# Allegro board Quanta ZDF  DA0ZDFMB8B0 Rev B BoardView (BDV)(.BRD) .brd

Outline 153.3 x 69.5 mm; copper layers: TOP, IN1, IN2, GND, IN3, IN4, IN5, BOTTOM. Coordinates in mm from the lower left corner of the outline.
Outline path: 0,62.4 arc(0.29,63.11) 1,63.4 17.2,63.4 arc(18.61,62.81) 19.2,61.4 19.2,52.9 arc(19.79,51.49) 21.2,50.9 56.5,50.9 arc(57.91,51.49) 58.5,52.9 58.5,65.5 arc(59.67,68.33) 62.5,69.5 148,69.5 arc(148.71,69.21) 149,68.5 149,65.2 152.3,65.2 arc(153.01,64.91) 153.3,64.2 153.3,6 arc(152.71,4.59) 151.3,4 88.1,4 arc(87.39,3.71) 87.1,3 87.1,1 arc(86.81,0.29) 86.1,0 9.2,0 arc(7.79,0.59) 7.2,2 7.2,20 4.2,20 arc(2.79,20.59) 2.2,22 2.2,40.1 13.45,40.1 arc(13.95,40.6) 13.45,41.1 13.45,46.65 arc(13.95,47.15) 13.45,47.65 2.2,47.65 2.2,47.75 1,47.75 arc(0.29,48.04) 0,48.75 0,51.73 4.27,51.73 arc(4.77,51.22) 5.27,51.73 5.27,60.68 arc(4.77,61.17) 4.27,60.68 0,60.68 0,62.4

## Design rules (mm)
constraint set DEFAULT: min track width 0.089
net group DFP-S3W10-T12345B: nets EAR_JACK_GND MIC_P
net group W5-T12345B: nets DVDD_CORE PP5000_PMIC
net group W6-T1234B: nets USB_C0_CC1 USB_C0_CC2
net group W10-T1234B: nets AMP_L_EN AMP_R_EN
net group W16-T12345B: nets DVDD_SRAM_PROC_B PP3000_EMMC
net group W20-T123B: nets DA7219_HPL HP_R
net group DFP-S3.5(3: nets 3V3_PCSCL 3V3_PCSDA SOC_I2C5_1V8_SCL SOC_I2C5_1V8_SDA SOC_I2C6_1V8_SCL SOC_I2C6_1V8_SDA
net group DFP-S3.5(3: nets AP_CTS_BT_RTS AP_RTS_BT_CTS AP_RXD1_BT_TXD AP_TXD1_BT_RXD CTP_I2C_SCL CTP_I2C_SDA EC_I2C1_1V8_SCL EC_I2C1_1V8_SDA EC_I2C2_1V8_SCL EC_I2C2_1V8_SDA EC_I2C_USB_C0_MUX_SCL EC_I2C_USB_C0_MUX_SDA I2C_SCL_INA I2C_SCL_INA_SERVO I2C_SDA_INA I2C_SDA_INA_SERVO SOC_I2C0_1V8_SCL SOC_I2C0_1V8_SDA SOC_I2C2_1V8_SCL SOC_I2C2_1V8_SDA SOC_I2C3_1V8_SCL SOC_I2C3_1V8_SDA SOC_I2C4_1V8_SCL SOC_I2C4_1V8_SDA
net group DFP-S3W3-T12345B: nets DVDD_CORE_PMIC_FB DVDD_CORE_PMIC_GND DVDD_GPU_PMIC_FB DVDD_GPU_PMIC_GND DVDD_PROC_B_PMIC_FB DVDD_PROC_B_PMIC_GND DVDD_PROC_L_PMIC_FB DVDD_PROC_L_PMIC_GND EMI_VDD2_FB EMI_VDD2_GND N57744014 N57744016 N57744064 N57744066 N57744104 N57744106 N57744144 N57744146 N57744176 N57744178 N57744224 N57744226 N57744256 N57744258 N57744304 N57744306 N57744336 N57744338 N57744932 N57744934 N57744959 N57744961 N57744999 N57745009 N57745825 N57745829 N57745845 N57745857 N57745883 N57745895 PP1800_ALW_N PP1800_ALW_P PP1800_EC_N PP1800_EC_P PP1800_H1_N PP1800_H1_P PP1800_WLAN_N PP1800_WLAN_P PP3300_ALW_N PP3300_ALW_P PP3300_CTP_N PP3300_CTP_P PP3300_EDP_DX_N PP3300_EDP_DX_P PP3300_H1_N PP3300_H1_P PP3300_WLAN_N PP3300_WLAN_P PP5000_PMIC_N PP5000_PMIC_P PP5000_VDRAM1_N PP5000_VDRAM1_P PPVAR_SYS_BL_N PPVAR_SYS_BL_P PPVAR_SYS_N PPVAR_SYS_P PPVAR_USB_C0_VBUS_N PPVAR_USB_C0_VBUS_P VBAT_IN_N VBAT_IN_P
net group DFP-S3W4-T12345B: nets AU_VIN1_N AU_VIN1_P EAR_MIC_N EAR_MIC_P
net group DFP-S5.9(5.9: nets EDP_AUX_N EDP_AUX_P EDP_TX0_N EDP_TX0_P EDP_TX1_N EDP_TX1_P USB2_DM USB2_DM_R USB2_DP USB2_DP_R USB2_HUB_P1_N USB2_HUB_P1_P USB2_HUB_P4_N USB2_HUB_P4_P USB2_WFC_N USB2_WFC_P USB_C0_USB2_L_N USB_C0_USB2_L_P USB_C0_USB2_N USB_C0_USB2_P
net group DFP-S5.9(5.9: nets EDP_AUX_C_N EDP_AUX_C_P EDP_TX0_C_N EDP_TX0_C_P EDP_TX1_C_N EDP_TX1_C_P USB2_A0_N USB2_A0_P USB2_HUB_P3_N USB2_HUB_P3_P
net group DFP-S6(5.8: nets CKDN CKDP DP_AUX_N DP_AUX_P DP_LN0_N DP_LN0_P DP_LN1_N DP_LN1_P DP_LN2_N DP_LN2_P DP_LN3_N DP_LN3_P DSI0_CKN DSI0_CKP DSI0_D0N DSI0_D0P DSI0_D1N DSI0_D1P DSI0_D2N DSI0_D2P DSI0_D3N DSI0_D3P L0DN L0DP L1DN L1DP L2DN L2DP L3DN L3DP TX0N TX0P TX1N TX1P TX2N TX2P TX3N TX3P TXAUXN TXAUXP USB_C0_RX1_C_N USB_C0_RX1_C_P USB_C0_RX1_N USB_C0_RX1_P USB_C0_RX2_C_N USB_C0_RX2_C_P USB_C0_RX2_N USB_C0_RX2_P USB_C0_TX1_C_N USB_C0_TX1_C_P USB_C0_TX1_N USB_C0_TX1_P USB_C0_TX2_C_N USB_C0_TX2_C_P USB_C0_TX2_N USB_C0_TX2_P
net group DFP-S6(5.8: nets H1_SBU1 H1_SBU2 N55392804 N55392806 N55392842 N55392848 N61132598 N61132650 USB_C0_SBU1 USB_C0_SBU1_MUX USB_C0_SBU2 USB_C0_SBU2_MUX
net group W2.3-T12345B: nets AU_HPL AU_HPR AU_REFN
net group W3-T12345B: nets VA12_PMU
net group W3.5(3: nets AUD_CLK_MISO AUD_CLK_MOSI AUD_DAT_MISO0 AUD_DAT_MISO1 AUD_DAT_MOSI1 AUD_SYNC_MISO AUD_SYNC_MOSI DMIC_DATA_1_R PWRAP_SPI0_CK PWRAP_SPI0_CSN PWRAP_SPI0_MI PWRAP_SPI0_MO SPI0_CLK SPI0_CSB SPI0_MI SPI0_MO
net group W3.5(3: nets AP_CLK26M_S0 AP_MSDC1_CLK AP_MSDC1_CMD AP_MSDC1_DAT0 AP_MSDC1_DAT1 AP_MSDC1_DAT2 AP_MSDC1_DAT3 AP_SPI_FLASH_CLK AP_SPI_FLASH_CS_L AP_SPI_FLASH_MISO AP_SPI_FLASH_MOSI AP_SPI_H1_CLK AP_SPI_H1_CS_L AP_SPI_H1_MISO AP_SPI_H1_MOSI AUD_DAT_MOSI0 BOOTBLOCK_EC_CLK BOOTBLOCK_EC_CMD BOOTBLOCK_EC_DAT0 DEBUG_SPI_FLASH_CS_L DEBUG_SPI_FLASH_HOLD_L DEBUG_SPI_FLASH_MISO DEBUG_SPI_FLASH_MOSI DEBUG_SPI_FLASH_SCK DISP_PWM DMIC_CLK DMIC_DATA_1 DPI_CK DPI_D0 DPI_D1 DPI_D2 DPI_D3 DPI_D4 DPI_D5 DPI_D6 DPI_D7 DPI_D8 DPI_D9 DPI_D10 DPI_D11 DPI_DE DPI_HSYNC DPI_VSYNC IT6505_CK IT6505_D0 IT6505_D1 IT6505_D2 IT6505_D3 IT6505_D4 IT6505_D5 IT6505_D6 IT6505_D7 IT6505_D8 IT6505_D9 IT6505_D10 IT6505_D11 IT6505_DE IT6505_HSYNC IT6505_VSYNC MSDC0_CLK MSDC0_CLK_EMMC MSDC0_CMD MSDC0_CMD_EMMC MSDC0_DAT0 MSDC0_DAT0_EMMC MSDC0_DAT1 MSDC0_DAT2 MSDC0_DAT3 MSDC0_DAT4 MSDC0_DAT5 MSDC0_DAT6 MSDC0_DAT7 MSDC0_DSL MSDC0_RSTB MSDC1_CLK MSDC1_CMD MSDC1_DAT0 MSDC1_DAT1 MSDC1_DAT2 MSDC1_DAT3 N54975848 N54975861 N54975866 N54975879 N54975900 N54975905 N56177260 N56177291 N56177312 N56177318 N60013740 N60013744 PANEL_BL_PWM_3V3 PMIC_CLK_WCN RTC32K_CK SPI2_CLK SPI2_CSB SPI2_MI SPI2_MO SPI_AP_EC_CLK SPI_AP_EC_CS_L SPI_AP_EC_MISO SPI_AP_EC_MOSI XO_CEL XO_SOC XO_WCN XTAL1 XTAL2
net group W4-T12345B: nets DVDD18_DIG EMI_VDDQ N46264414 PP5000_SMPS
net group W5-T123B: nets N60721677
net group W5-T1234B: nets JACKDET_L
net group W6-T12345B: nets EMMC_VDDI N52164418 N52164422 PP1800_ALW PP1800_AP PP1800_H1 PP1800_SENSOR PP3300_CTP PP3300_H1 PP3300_INA PP5000_VCORE PP5000_VDRAM1 PP5000_VGPU PP5000_VMODEM PP5000_VPROC11 PP5000_VPROC12 PP5000_VS1 PP5000_VS2 TX_OVDD VCAMD_PMU VCORE VGPU VPROC11 VPROC12 VRTC28 VS1 VS1_PMU VS2 VS2_PMU VSIM1_PMU
net group W7-T12345B: nets AVDD18_SOC DVDD_SRAM_CORE DVDD_VSRAM_GPU_PMU EMI_VDD2 PP3300_ALW PP3300_S3 TX_AVCC TX_PVCC1
net group W8-T1B: nets HPCSN HPCSP N56253380 N56253382
net group W8-T123B: nets DA7219_HPR DA7219_MIC DA7219_MICBIAS HP_L N52164405 N52164407
net group W8-T12345B: nets AU_MICBIAS0 AU_MICBIAS1 DVDD_PROC_L DVDD_SRAM_PROC_L PP1800_EC PP1800_EMMC PP1800_IT6505_D PP1800_WLAN PP3000_EMMC_R PP3300_EDP_DX PP3300_WLAN PPVAR_SYS PPVAR_USB_C0_VBUS TX_PVCC0 TX_PVCC2 TX_XVCC18 VAUD28_PMU VAUX18_PMU VBIF28_PMU VCAMA2_PMU VCAMA_PMU VCAMIO_PMU VEFUSE_PMU VIO18_MT6358 VIO18_PMU_AP VMC_PMU VUSB_PMU VXO22_PMU
net group W9-T12345B: nets PP1800_LPDDR
net group W10-T123B: nets DA7219_MIC_N DA7219_MIC_P RING2 RING2_SENSE SLEEVE SLEEVE_SENSE
net group W10-T12345B: nets 227E_RING2_SENSE 227E_SLEEVE_SENSE AMP_R_POWER AVSS28_AUD GND_VREF MT6358_HPL MT6358_HPR PP1800_S3 PPVAR_BATT VCN18_PMU VREF
net group W15-T12345B: nets DA7219_VDD DA7219_VDD_MIC DA7219_VDDIO N52164426 PP1800_IT6505_A PP3300_EC PP3300_SERVO_INA TS3A227E_POWER VDRAM1
net group W20-T12345B: nets 227E_RING2 227E_SLEEVE 227E_TIP AMP_L_POWER DVDD_GPU DVDD_PROC_B N52164464 PP3300_EDP_DX_R
net group W30-T123B: nets N54517064 N54517066 N54517443 N54517445 SPK_L_N SPK_L_P SPK_R_N SPK_R_P

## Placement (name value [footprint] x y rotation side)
BATT_DISABLE_ODL_MTK  *TP  [TP2050]  51.16 18.68 180 bottom
C1  0.1U/6.3V_2  [C0201]  33.38 24.26 180 bottom
C2  0.1U/6.3V_2  [C0201]  32.6 26.83 270 bottom
C3  0.1U/6.3V_2  [C0201]  31.83 26.83 270 bottom
C4  0.1U/6.3V_2  [C0201]  27.64 16.59 90 bottom
C6  0.1U/6.3V_2  [C0201]  32.11 17.15 90 bottom
C7  0.1U/6.3V_2  [C0201]  23.6 28.96 180 bottom
C8  0.1U/6.3V_2  [C0201]  23.6 28.2 180 bottom
C10  22U/6.3V_6  [C0603]  33.76 28.71 180 top
C11  0.1U/6.3V_2  [C0201]  22.84 17.41 0 bottom
C12  1U/6.3V_2  [C0201]  22.84 16.64 0 bottom
C13  0.1U/6.3V_2  [C0201]  21.14 19.97 270 bottom
C14  1U/6.3V_2  [C0201]  21.9 19.97 270 bottom
C15  0.1U/6.3V_2  [C0201]  21.83 17.41 180 bottom
C16  1U/6.3V_2  [C0201]  21.83 16.64 180 bottom
C17  0.1U/6.3V_2  [C0201]  22.72 18.42 270 bottom
C18  1U/6.3V_2  [C0201]  21.95 18.42 270 bottom
C19  0.1U/6.3V_2  [C0201]  28.41 16.62 90 bottom
C20  0.1U/6.3V_2  [C0201]  30.31 26.83 270 bottom
C21  0.1U/6.3V_2  [C0201]  27.8 15.65 0 bottom
C22  0.1U/6.3V_2  [C0201]  31.22 17.15 90 bottom
C23  0.1U/6.3V_2  [C0201]  33.38 22.23 180 bottom
C24  22U/6.3V_6  [C0603]  31.1 28.71 180 top
C25  0.1U/6.3V_2  [C0201]  23.48 21.6 0 bottom
C26  0.1U/6.3V_2  [C0201]  23.27 25.15 0 bottom
C27  0.1U/6.3V_2  [C0201]  23.48 22.74 0 bottom
C28  0.1U/6.3V_2  [C0201]  23.48 23.88 0 bottom
C29  22U/6.3V_6  [C0603]  21.09 20.17 0 top
C44  20P/25V_2  [C0201]  20.99 16.82 90 top
C45  20P/25V_2  [C0201]  20.99 15.7 270 top
C46  1U/6.3V_2  [C0201]  24.11 26.55 180 bottom
C141  4700p/25V_4  [C0402]  98.15 12.73 180 bottom
C175  0.1u/16V_4  [C0402]  24.37 31.76 270 top
C228  0.1U/6.3V_2  [C0201]  60.82 40.47 0 top
C229  0.1U/6.3V_2  [C0201]  60.82 39.76 0 top
C238  10U/6.3V_4  [C0402_2]  71.48 40.65 270 top
C239  10U/6.3V_4  [C0402_2]  68.82 34.4 90 top
C240  0.1U/6.3V_2  [C0201]  67.85 34.68 90 top
C243  *100p/50V_2  [C0201]  71.28 35.44 270 top
C246  10u/25V_6  [C0603]  57.49 47.3 270 bottom
C251  1U/6.3V_2  [C0201]  72.25 34.45 90 top
C299  1u/6.3V_4  [C0402]  95.11 8.9 270 top
C333  *0.1U/6.3V_2  [C0201]  36.08 27.97 0 top
C368  0.1U/6.3V_2  [C0201]  54.08 9.79 270 bottom
C375  22u/25V_8  [C0805]  91.17 14.74 270 bottom
C412  *0.1U/6.3V_2  [C0201]  42.78 4.83 0 top
C414  *0.1U/6.3V_2  [C0201]  41.38 11.31 180 bottom
C415  *0.1U/6.3V_2  [C0201]  44.69 11.31 0 bottom
C426  1u/25V_4  [C0402]  118.73 26.8 0 bottom
C431  10U/6.3V_6  [C0603]  45.07 43.95 270 top
C434  1U/6.3V_2  [C0201]  48.62 14.36 180 top
C436  4.7u/25V_6  [C0603]  131.3 28.45 0 top
C437  4.7u/25V_6  [C0603]  126.75 38.56 90 top
C438  22u/25V_8  [C0805]  122.03 40.52 270 bottom
C439  4.7u/25V_6  [C0603]  125.14 37.05 90 top
C440  0.22u/50V_6  [C0603]  124.97 27.21 270 top
C444  *2CM@4.7u/10V_4  [C0402]  123.81 64.17 180 top
C447  4.7u/25V_6  [C0603]  38.59 46.36 270 top
C457  22u/25V_8  [C0805]  120 40.52 270 bottom
C487  *2.2u/10V_4  [C0402]  140.72 43.64 180 bottom
C488  0.22u/50V_6  [C0603]  129.75 31.38 180 top
C491  0.1u/25V_2  [C0201]  120 26.3 90 bottom
C492  22u/25V_8  [C0805]  102.22 13.19 0 bottom
C493  0.1u/25V_2  [C0201]  35.67 48.11 180 top
C495  0.01u/50V_4  [C0402]  119.87 32.59 0 top
C503  22u/25V_8  [C0805]  117.97 40.52 270 bottom
C504  22u/25V_8  [C0805]  124.01 40.52 270 bottom
C518  *1000p/25V_4  [C0402]  9.63 60.48 270 bottom
C526  0.1U/6.3V_2  [C0201]  60.82 41.2 0 top
C527  0.1U/6.3V_2  [C0201]  60.82 41.92 0 top
C533  0.1u/50V_4  [C0402]  123.55 38.16 90 top
C594  0.01u/50V_4  [C0402]  119.87 31.63 0 top
C748  0.01u/10V_2  [C0201]  24.11 30.38 0 top
C749  4.7U/10V_4  [C0402]  17.13 35.69 270 top
C1001  0.1U/6.3V_2  [C0201]  86.57 31.33 90 top
C1002  1U/6.3V_2  [C0201]  86.27 30.44 0 top
C1003  1U/6.3V_2  [C0201]  85.4 30.7 90 top
C1004  1U/6.3V_2  [C0201]  87.82 31.17 270 top
C1005  0.1U/6.3V_2  [C0201]  83.42 41.02 90 bottom
C1006  1U/6.3V_2  [C0201]  83.22 42.18 90 bottom
C1009  0.1U/6.3V_2  [C0201]  85.68 31.55 0 top
C1010  0.1U/6.3V_2  [C0201]  86.07 36.01 180 bottom
C1011  0.1U/6.3V_2  [C0201]  86.04 35.3 180 bottom
C1502  1U/6.3V_2  [C0201]  87.87 33.41 90 bottom
C1503  1U/6.3V_2  [C0201]  86.98 34.55 90 bottom
C1701  *0.1U/6.3V_2  [C0201]  89.44 28.99 90 top
C1702  0.1U/6.3V_2  [C0201]  85.66 28.08 180 top
C1703  0.1U/6.3V_2  [C0201]  85.66 28.82 180 top
C1704  0.1U/6.3V_2  [C0201]  85.66 29.73 180 top
C1706  0.1U/6.3V_2  [C0201]  84.69 29.96 270 top
C1707  0.1U/6.3V_2  [C0201]  84.51 28.77 0 top
C1709  0.1U/6.3V_2  [C0201]  84.51 28.05 0 top
C1808  1U/6.3V_2  [C0201]  88.88 39.22 180 bottom
C1810  1U/6.3V_2  [C0201]  87.7 40.36 0 bottom
C1811  2.2U/6.3V_2  [C0201]  87.69 41.08 180 bottom
C1812  1U/6.3V_2  [C0201]  87.7 39.65 0 bottom
C1813  1U/6.3V_2  [C0201]  85.09 36.19 270 bottom
C1814  1U/6.3V_2  [C0201]  82.81 35.64 0 bottom
C1815  1U/6.3V_2  [C0201]  82.83 34.9 0 bottom
C1816  1U/6.3V_2  [C0201]  82.71 33.87 0 bottom
C1817  1U/6.3V_2  [C0201]  82.9 37.35 90 bottom
C1818  0.1U/6.3V_2  [C0201]  87.33 38.06 270 bottom
C1819  1U/6.3V_2  [C0201]  83.62 37.35 90 bottom
C1820  0.1U/6.3V_2  [C0201]  88.04 38.06 270 bottom
C1821  1U/6.3V_2  [C0201]  84.32 38.51 270 bottom
C1822  1U/6.3V_2  [C0201]  84.37 36.19 270 bottom
C1823  1U/6.3V_2  [C0201]  84.37 37.35 90 bottom
C1824  0.1U/6.3V_2  [C0201]  85.68 33.53 0 bottom
C1825  0.1U/6.3V_2  [C0201]  86.03 34.57 0 bottom
C1826  1U/6.3V_2  [C0201]  87.69 38.92 0 bottom
C1827  1U/6.3V_2  [C0201]  85.1 37.35 90 bottom
C1828  1U/6.3V_2  [C0201]  88.87 39.97 180 bottom
C1829  1U/6.3V_2  [C0201]  82.81 36.35 0 bottom
C1830  1U/6.3V_2  [C0201]  86.48 39.22 0 bottom
C1831  1U/6.3V_2  [C0201]  86.48 39.94 0 bottom
C1832  1U/6.3V_2  [C0201]  84.88 40.86 90 bottom
C1833  1U/6.3V_2  [C0201]  85.61 40.17 90 bottom
C1834  1U/6.3V_2  [C0201]  84.16 40.86 90 bottom
C1835  1U/6.3V_2  [C0201]  86.47 38.5 0 bottom
C1836  0.1U/6.3V_2  [C0201]  85.83 36.89 270 bottom
C1837  0.1U/6.3V_2  [C0201]  88.76 37.95 90 bottom
C1838  0.1U/6.3V_2  [C0201]  81.8 35.45 0 bottom
C1839  0.1U/6.3V_2  [C0201]  81.75 37.12 90 bottom
C1840  1U/6.3V_2  [C0201]  83.66 36.19 270 bottom
C1841  1U/6.3V_2  [C0201]  84.95 34.84 180 bottom
C1842  1U/6.3V_2  [C0201]  84.23 34.1 180 bottom
C1843  1U/6.3V_2  [C0201]  83.59 38.51 270 bottom
C2001  1U/6.3V_2  [C0201]  104.98 34.33 90 top
C2002  10U/6.3V_4  [C0402_2]  80.96 42.13 0 bottom
C2003  22U/6.3V_6  [C0603]  83.57 30.62 270 top
C2004  10U/6.3V_4  [C0402_2]  102.37 37.43 0 top
C2005  10U/6.3V_6  [C0603]  82.15 30.61 90 top
C2007  10U/6.3V_4  [C0402_2]  102.37 39.33 0 top
C2008  10U/6.3V_4  [C0402_2]  80.96 40.86 0 bottom
C2009  10U/6.3V_4  [C0402_2]  103.89 42.99 180 top
C2010  10U/6.3V_4  [C0402_2]  91.55 38.49 90 bottom
C2011  10U/6.3V_4  [C0402_2]  88.45 36.25 270 bottom
C2013  *4.7U/6.3V_4  [C0402_2]  105.98 43.21 90 top
C2016  *10U/6.3V_4  [C0402_2]  102.37 36.23 0 top
C2021  10U/6.3V_6  [C0603]  80.73 30.18 90 top
C2023  4.7U/6.3V_4  [C0402_2]  104.01 34.08 90 top
C2024  4.7U/6.3V_4  [C0402_2]  108.36 43.29 270 top
C2025  10U/6.3V_4  [C0402_2]  102.37 40.53 0 top
C2026  10U/6.3V_4  [C0402_2]  88.78 41.64 270 bottom
C2027  10U/6.3V_4  [C0402_2]  91.88 46.09 270 bottom
C2028  4.7U/6.3V_4  [C0402_2]  107.17 43.29 90 top
C2029  10U/6.3V_4  [C0402_2]  79.89 50 180 bottom
C2030  10U/6.3V_4  [C0402_2]  79.89 48.73 180 bottom
C2031  10U/6.3V_4  [C0402_2]  79.89 47.46 180 bottom
C2032  22U/6.3V_6  [C0603]  111.74 43.32 180 top
C2101  2.2U/6.3V_4  [C0402]  112.81 36.68 0 top
C2102  2.2U/6.3V_4  [C0402]  111.59 38.42 270 top
C2103  2.2U/6.3V_4  [C0402]  114.26 47.41 270 top
C2105  1U/6.3V_2  [C0201]  111.13 38.32 0 bottom
C2106  1U/6.3V_2  [C0201]  112.73 41.47 180 bottom
C2108  1U/6.3V_2  [C0201]  112.83 34.2 0 bottom
C2111  2.2U/6.3V_4  [C0402]  112.81 35.71 180 top
C2112  1U/6.3V_2  [C0201]  115.81 37.6 0 top
C2113  22U/6.3V_6  [C0603]  101.35 29.93 90 top
C2116  4.7U/6.3V_4  [C0402_2]  104.02 32.27 270 top
C2117  2.2U/6.3V_4  [C0402]  110.85 41.69 90 top
C2120  1U/6.3V_2  [C0201]  113.42 38.19 90 top
C2121  1U/6.3V_2  [C0201]  111.64 34.61 180 top
C2124  1U/6.3V_2  [C0201]  112.66 39.92 0 top
C2125  1U/6.3V_2  [C0201]  112.4 37.55 0 bottom
C2129  22U/6.3V_6  [C0603]  113.04 45.83 180 top
C2130  22U/6.3V_6  [C0603]  102.78 29.93 90 top
C2132  4.7U/6.3V_4  [C0402_2]  101.86 28.79 90 bottom
C2133  1U/6.3V_2  [C0201]  104.5 37.88 180 bottom
C2134  1U/6.3V_2  [C0201]  104.53 36.79 180 bottom
C2135  1U/6.3V_2  [C0201]  95.64 45.3 0 top
C2136  4.7U/6.3V_4  [C0402_2]  106.03 28.91 90 top
C2138  0.1U/6.3V_2  [C0201]  111.13 40.73 180 bottom
C2139  1U/6.3V_2  [C0201]  111.84 36.16 270 bottom
C2140  0.1U/6.3V_2  [C0201]  111.08 36.16 270 bottom
C2141  1U/6.3V_2  [C0201]  107.7 38.2 270 bottom
C2142  1U/6.3V_2  [C0201]  110.9 44.62 0 top
C2144  2.2U/6.3V_4  [C0402]  80.12 27.74 180 top
C2145  2.2U/6.3V_4  [C0402]  112.2 41.03 180 top
C2146  2.2U/6.3V_4  [C0402]  96.91 44.41 90 bottom
C2147  2.2U/6.3V_4  [C0402]  114.31 39.21 180 top
C2148  2.2U/6.3V_4  [C0402]  112.81 44.64 180 top
C2149  4.7U/6.3V_4  [C0402_2]  109.76 43.27 270 top
C2302  *1U/6.3V_2  [C0201]  109.76 41.44 0 bottom
C2303  1u/25V_4  [C0402]  111.23 43.14 180 bottom
C4004  1U/6.3V_2  [C0201]  86.55 41.29 270 bottom
C4005  1U/6.3V_2  [C0201]  84.62 42.66 90 bottom
C4006  1U/6.3V_2  [C0201]  85.83 41.29 270 bottom
C4007  1U/6.3V_2  [C0201]  84.34 41.77 180 bottom
C4011  1U/6.3V_2  [C0201]  85.68 43.19 180 bottom
C4012  1U/6.3V_2  [C0201]  85.4 42.28 90 bottom
C4013  1U/6.3V_2  [C0201]  87.69 41.9 180 bottom
C4014  1U/6.3V_2  [C0201]  86.67 42.35 0 bottom
C4101  0.1U/6.3V_2  [C0201]  92.77 43.62 270 top
C4202  *0.1U/6.3V_2  [C0201]  90.28 45.1 0 top
C4203  *1U/6.3V_2  [C0201]  91.27 45.12 0 top
C4301  0.1U/6.3V_2  [C0201]  92.85 36.25 180 bottom
C4302  1U/6.3V_2  [C0201]  93.25 35.34 0 bottom
C4401  0.1U/6.3V_2  [C0201]  105.86 59.93 90 bottom
C4402  0.1U/6.3V_2  [C0201]  104.09 58.53 180 bottom
C4403  4.7U/6.3V_4  [C0402]  111.84 50.81 90 top
C4404  0.1U/6.3V_2  [C0201]  107.9 58.53 270 bottom
C4405  0.1U/6.3V_2  [C0201]  102.31 58.4 90 bottom
C4406  2.2U/6.3V_4  [C0402]  108.58 56.4 270 bottom
C4407  0.1U/6.3V_2  [C0201]  84.86 58.89 180 top
C4408  2.2U/6.3V_4  [C0402]  86.31 58.89 180 top
C4409  1U/6.3V_2  [C0201]  83.63 48.85 270 bottom
C4410  1U/6.3V_2  [C0201]  91.42 50.24 180 bottom
C4411  1U/6.3V_2  [C0201]  86.97 48.87 90 bottom
C4412  1U/6.3V_2  [C0201]  87.29 55.97 270 bottom
C4413  1U/6.3V_2  [C0201]  92.55 54.09 270 bottom
C4414  1U/6.3V_2  [C0201]  89.78 48.94 90 bottom
C4415  1U/6.3V_2  [C0201]  82.08 55.29 90 bottom
C4416  1U/6.3V_2  [C0201]  89.08 54.01 0 bottom
C4417  1U/6.3V_2  [C0201]  81.34 49.5 180 bottom
C4418  1U/6.3V_2  [C0201]  79.72 53.17 0 bottom
C4419  0.1U/6.3V_2  [C0201]  102.51 56.13 90 bottom
C4420  1U/6.3V_2  [C0201]  103.27 56.13 270 bottom
C4421  1U/6.3V_2  [C0201]  82.92 52.28 180 bottom
C4422  1U/6.3V_2  [C0201]  78.35 53.75 90 bottom
C4423  1U/6.3V_2  [C0201]  77.96 47.5 180 bottom
C4424  1U/6.3V_2  [C0201]  90.97 52.66 270 bottom
C4425  1U/6.3V_2  [C0201]  88.28 53.19 0 bottom
C4426  1U/6.3V_2  [C0201]  84.57 56.42 180 bottom
C4427  22U/6.3V_6  [C0603]  95.76 49.65 90 top
C5001  0.1U/6.3V_2  [C0201]  81.03 43.14 180 bottom
C5002  0.1U/6.3V_2  [C0201]  81.03 43.9 180 bottom
C6101  1U/6.3V_2  [C0201]  107.88 30.32 0 top
C6102  1U/6.3V_2  [C0201]  108.31 34.07 90 bottom
C6103  1U/6.3V_2  [C0201]  109.08 34.07 90 bottom
C6104  2.2U/6.3V_4  [C0402]  107.48 33.26 90 top
C6105  4.7U/6.3V_4  [C0402_2]  107.73 31.53 90 top
C6106  4.7U/6.3V_4  [C0402_2]  106.33 34.05 90 top
C6209  *33P/50V_4  [C0402]  104.85 26.71 270 bottom
C6221  *33P/50V_4  [C0402]  105.82 26.73 270 bottom
C6229  *1U/6.3V_4  [C0402]  107.76 28.3 0 bottom
C6230  *1U/6.3V_4  [C0402]  107.76 27.29 0 bottom
C6324  *33P/50V_4  [C0402]  28.91 9.53 0 top
C6329  *33P/50V_4  [C0402]  26.15 9.49 180 top
C6401  *1U/6.3V_2  [C0201]  143.11 30.23 270 top
C6404  *0.1U/6.3V_2  [C0201]  142.22 33.28 0 top
C6701  1U/6.3V_2  [C0201]  92.41 36.61 0 top
C6702  1U/6.3V_2  [C0201]  92.26 34.93 180 bottom
C6901  1U/6.3V_2  [C0201]  81.03 38.47 0 bottom
C7101  0.1U/6.3V_2  [C0201]  89.75 42.27 270 bottom
C7102  1U/6.3V_2  [C0201]  92.77 42.5 270 top
C7104  1U/6.3V_2  [C0201]  94.04 43.9 0 top
C7210  1U/6.3V_2  [C0201]  93.63 42.81 0 top
C7405  0.1U/6.3V_2  [C0201]  88.73 28.99 90 top
C7406  0.1U/6.3V_2  [C0201]  95.77 27.08 270 top
C7407  0.1U/6.3V_2  [C0201]  90.15 28.99 90 top
C8001  *10p/50V_2  [C0201]  115.2 35.52 0 top
C8101  1U/6.3V_2  [C0201]  108.34 34.13 90 top
C8201  0.1U/6.3V_2  [C0201]  108.62 38.42 0 bottom
C8202  22U/6.3V_6  [C0603]  115.96 39.59 90 top
C9016  0.1U/6.3V_2  [C0201]  31.07 26.83 270 bottom
C9017  0.1U/6.3V_2  [C0201]  33.38 23.5 180 bottom
C9018  *33P/50V_4  [C0402]  23.86 9.38 0 top
C9019  *33P/50V_4  [C0402]  20.71 6.44 180 top
C9020  10U/6.3V_6  [C0603]  32.27 7.63 90 top
C9021  0.1U/6.3V_2  [C0201]  33.38 7.86 90 top
C9022  10U/6.3V_6  [C0603]  21.29 3.51 90 top
C9023  0.1U/6.3V_2  [C0201]  22.51 3.21 90 top
C9035  0.1U/6.3V_2  [C0201]  21.06 25.15 180 top
C9036  0.1U/6.3V_2  [C0201]  21.06 25.91 180 top
C9047  1U/6.3V_4  [C0402]  12.05 27.18 0 top
C9048  1U/6.3V_4  [C0402]  10.27 27.18 0 top
C9049  1U/6.3V_4  [C0402]  8.49 27.06 0 top
C9050  1U/6.3V_4  [C0402]  8.87 30.36 0 top
C9051  1U/6.3V_4  [C0402]  8.87 32.39 0 top
C9052  1U/6.3V_4  [C0402]  8.87 31.38 0 top
C9053  1U/6.3V_4  [C0402]  8.87 28.2 0 top
C9054  1U/6.3V_4  [C0402]  8.87 29.22 0 top
C9055  1U/6.3V_4  [C0402]  10.9 35.69 90 top
C9056  1U/6.3V_4  [C0402]  13.98 31.76 270 top
C9057  1U/6.3V_4  [C0402]  8.87 33.41 0 top
C9058  1U/6.3V_4  [C0402]  13.98 28.53 90 top
C9061  1U/6.3V_2  [C0201]  43.16 33 0 bottom
C9063  1U/6.3V_2  [C0201]  46.74 32.95 90 bottom
C9066  1U/6.3V_2  [C0201]  30.72 31.88 90 top
C9067  1U/6.3V_2  [C0201]  32.37 30.11 270 top
C10350  0.1U/6.3V_2  [C0201]  130.41 53.85 90 top
C10354  2.2U/6.3V_4  [C0402]  121.65 48.65 0 top
C10355  1U/6.3V_2  [C0201]  131.43 50.68 0 top
C10356  0.1U/6.3V_2  [C0201]  131.43 51.44 0 top
C10357  0.1U/6.3V_2  [C0201]  131.43 49.92 0 top
C10358  0.1U/6.3V_2  [C0201]  131.43 49.16 0 top
C10359  0.1U/6.3V_2  [C0201]  57.13 13.34 90 top
C10365  1U/6.3V_2  [C0201]  53.96 18.42 0 bottom
C10367  0.1U/6.3V_2  [C0201]  54.59 16.77 0 bottom
C10368  0.1U/6.3V_2  [C0201]  56.35 15.75 90 bottom
C10370  1U/6.3V_2  [C0201]  60.18 17.1 270 top
C10372  0.1U/6.3V_2  [C0201]  54.64 19.18 0 bottom
C10373  0.1U/6.3V_2  [C0201]  59.42 17.1 270 top
C10374  *10p/50V_2  [C0201]  115.2 34.71 0 top
C10378  0.1U/6.3V_2  [C0201]  115.17 57.88 0 top
C10379  0.1U/6.3V_2  [C0201]  129.27 47.55 180 top
C10380  1U/6.3V_2  [C0201]  133.21 17.41 270 top
C10381  1U/6.3V_2  [C0201]  131.3 20.33 90 top
C10382  *0.1U/6.3V_2  [C0201]  13.8 13.52 180 top
C10383  *0.1U/6.3V_2  [C0201]  43.42 26.55 0 top
C10384  *0.1U/6.3V_2  [C0201]  123.55 18.68 180 top
C10385  *0.1U/6.3V_2  [C0201]  42.53 25.41 270 top
C10386  *0.1U/6.3V_2  [C0201]  43.59 29.04 0 top
C10387  *0.1U/6.3V_2  [C0201]  12.68 20.5 0 top
C10388  *0.1U/6.3V_2  [C0201]  10.14 14.92 180 top
C10389  *0.1U/6.3V_2  [C0201]  12.68 13.52 180 top
C10390  *0.1U/6.3V_2  [C0201]  118.09 13.85 180 top
C10391  *0.1U/6.3V_2  [C0201]  120.48 11.82 90 top
C10392  *0.1U/6.3V_2  [C0201]  124.82 15.37 270 top
C10393  1U/6.3V_2  [C0201]  129.01 15.25 90 top
C10394  1U/6.3V_2  [C0201]  128.76 20.33 90 top
C10395  *1000p/50V_2  [C0201]  130.41 20.33 90 top
C10396  *1000p/50V_2  [C0201]  129.52 20.33 90 top
C10399  *0.1U/6.3V_2  [C0201]  54.57 39.22 0 top
C10400  *0.1U/6.3V_2  [C0201]  49.59 40.14 180 top
C10401  *0.1U/6.3V_2  [C0201]  50.68 36.99 180 top
C10402  *0.1U/6.3V_2  [C0201]  56.6 42.73 0 top
C10412  0.1U/6.3V_2  [C0201]  26.06 43.03 180 top
C10413  0.1u/25V_2  [C0201]  26.75 45.35 0 bottom
C10420  0.1U/6.3V_2  [C0201]  133.28 59.85 90 top
C10421  0.1U/6.3V_2  [C0201]  132.52 59.85 90 top
C10422  0.1U/6.3V_2  [C0201]  139.7 63.1 270 top
C10423  0.1U/6.3V_2  [C0201]  131.76 59.85 90 top
C10424  0.1U/6.3V_2  [C0201]  133.66 55.43 270 bottom
C10425  0.1U/6.3V_2  [C0201]  129.4 50.04 0 top
C10426  0.1u/25V_4  [C0402]  71.05 19.41 180 bottom
C10427  22u/10V_6  [C0603]  76.46 11.89 180 bottom
C10428  22u/10V_6  [C0603]  76.46 13.32 180 bottom
C10430  10u/25V_8  [C0805]  60.56 15.88 90 bottom
C10431  *0.1U/6.3V_2  [C0201]  129.29 57.31 0 bottom
C10432  *0.1U/6.3V_2  [C0201]  127.67 58.98 270 bottom
C10433  *0.1U/6.3V_2  [C0201]  123 31.5 90 bottom
C10434  *0.1U/6.3V_2  [C0201]  122.28 59.87 90 bottom
C10435  *0.1U/6.3V_2  [C0201]  130.62 57.31 180 bottom
C10436  *0.1U/6.3V_2  [C0201]  117.71 31.55 90 bottom
C10437  22u/10V_6  [C0603]  61.53 27.13 180 bottom
C10438  1U/6.3V_2  [C0201]  86.85 33.28 180 bottom
C10439  1U/6.3V_2  [C0201]  87.74 34.55 90 bottom
C10440  *1U/6.3V_2  [C0201]  88.5 34.55 90 bottom
C10442  *1U/6.3V_2  [C0201]  11.54 23.25 270 top
C10443  *1U/6.3V_2  [C0201]  12.3 23.25 270 top
C10444  *100p/25V_2  [C0201]  106.54 28.1 270 bottom
C10445  *33P/50V_4  [C0402]  105.67 28.49 270 bottom
C10446  *0.1U/6.3V_2  [C0201]  143.87 30.23 270 top
C10447  1N/50V_4  [C0402]  108.39 26.9 90 top
C10448  *220P/50V_4  [C0402]  9.86 56.67 0 top
C10449  *220P/50V_4  [C0402]  9.06 51.61 0 bottom
C10451  *1u/50V_6  [C0603]  120.12 30.38 0 top
C10452  *470p/25V_2  [C0201]  119.54 33.69 180 top
C10453  0.015u/25V_4  [C0402]  119.44 34.93 270 top
C10454  1U/6.3V_2  [C0201]  72.37 27.64 270 top
C10455  0.1U/6.3V_2  [C0201]  72.6 24.21 180 top
C10456  0.1U/6.3V_2  [C0201]  64.42 27.39 270 top
C10457  0.1U/6.3V_2  [C0201]  137.04 40.04 180 bottom
C10458  0.1U/6.3V_2  [C0201]  65.79 32.29 90 top
C10460  *ECO@1U/6.3V_2  [C0201]  149.41 40.49 180 top
C10461  18p/50V_2  [C0201]  68.69 23.7 0 top
C10462  18p/50V_2  [C0201]  65.92 23.68 180 top
C10468  4.7U/6.3V_4  [C0402]  82.56 38.77 270 bottom
C10469  0.1U/6.3V_2  [C0201]  122.54 57.99 180 top
C10472  10U/6.3V_4  [C0402_2]  93.33 37.24 0 bottom
C10473  10U/6.3V_4  [C0402_2]  83.9 39.69 180 bottom
C10474  10U/6.3V_4  [C0402_2]  82.43 40.54 270 bottom
C10475  10U/6.3V_4  [C0402_2]  80.96 39.59 0 bottom
C10478  10U/6.3V_4  [C0402_2]  88.3 46.09 270 bottom
C10479  10U/6.3V_4  [C0402_2]  89.49 46.09 270 bottom
C10480  10U/6.3V_4  [C0402_2]  90.38 36.33 270 bottom
C10481  10U/6.3V_4  [C0402_2]  85.38 38.72 270 bottom
C10482  1U/6.3V_2  [C0201]  133.36 58.73 180 top
C10483  *1U/6.3V_2  [C0201]  110.73 33.61 0 top
C10484  *1U/6.3V_2  [C0201]  111.59 35.82 270 top
C10485  *1U/6.3V_2  [C0201]  111.57 40.09 0 top
C10486  *1U/6.3V_2  [C0201]  114.18 38.19 90 top
C10488  *1U/6.3V_2  [C0201]  99.83 33.11 180 top
C10489  2200p/50V_4  [C0402]  47.2 29.09 90 bottom
C10491  1u/25V_4  [C0402]  40.27 46.36 180 top
C10492  1u/25V_4  [C0402]  40.27 47.33 180 top
C10493  *680p/50V_6  [C0603]  139.17 35.92 0 bottom
C10494  *680p/50V_6  [C0603]  142.86 23.5 270 bottom
C10495  *1u/25V_4  [C0402]  119.99 27.8 180 bottom
C10496  0.22u/25V_4  [C0402]  118.18 27.81 0 bottom
C10499  22u/25V_8  [C0805]  123.48 25.66 270 bottom
C10500  22u/25V_8  [C0805]  121.5 25.66 270 bottom
C10501  22u/25V_8  [C0805]  111.92 11.46 90 bottom
C10502  0.1U/6.3V_2  [C0201]  139.43 11.06 90 top
C10503  0.1U/6.3V_2  [C0201]  135.75 18.8 270 top
C10504  0.1U/6.3V_2  [C0201]  145.25 18.55 270 top
C10505  1U/6.3V_2  [C0201]  145.65 16.41 0 top
C10508  22u/25V_8  [C0805]  109.94 11.46 90 bottom
C10509  0.1U/6.3V_2  [C0201]  60.82 43.36 0 top
C10510  0.1U/6.3V_2  [C0201]  60.82 42.65 0 top
C10525  1U/6.3V_2  [C0201]  47.25 39.73 180 top
C10533  1U/6.3V_2  [C0201]  61.35 15.4 270 top
C10534  1U/6.3V_2  [C0201]  60.71 13.37 90 top
C10535  *1U/6.3V_2  [C0201]  41.26 11.18 90 top
C10538  *1U/6.3V_2  [C0201]  38.72 12.63 0 top
C10539  *1U/6.3V_2  [C0201]  46.85 11.56 90 top
C10540  *1U/6.3V_2  [C0201]  43.16 12.71 90 top
C10550  *0.1U/6.3V_2  [C0201]  37.57 22.61 0 bottom
C10551  *0.1U/6.3V_2  [C0201]  38.16 16.31 270 bottom
C10552  1U/6.3V_2  [C0201]  114.69 41.24 0 top
C10566  1u/25V_4  [C0402]  34.73 45.68 270 top
C10570  0.1u/50V_4  [C0402]  28.61 44.35 270 top
C10571  4.7u/25V_6  [C0603]  33.54 46.51 90 top
C10575  *0.1U/6.3V_2  [C0201]  40.37 21.85 0 bottom
C10576  *0.1U/6.3V_2  [C0201]  38.87 16.34 270 bottom
C10604  0.47u/6.3V_2  [C0201]  18.14 42.3 180 top
C10605  8.2p/50V_2  [C0201]  109.71 32.72 180 top
C10606  8.2p/50V_2  [C0201]  110.73 32.72 0 top
C10610  1U/6.3V_2  [C0201]  26.88 38.74 90 bottom
C10613  10U/6.3V_4  [C0402_2]  77.99 48.73 0 bottom
C10614  10U/6.3V_4  [C0402_2]  77.96 49.92 0 bottom
C10619  2.2U/6.3V_4  [C0402]  87.21 43.22 180 bottom
C10620  *0.1u/10V_2  [C0201]  57.26 3.69 270 top
C10621  *ALS@1U/10V_2  [C0201]  147.38 37.85 270 top
C10622  10u/25V_6  [C0603]  133.1 42.07 270 bottom
C10623  1U/6.3V_2  [C0201]  70.11 24.06 0 top
C10624  10U/6.3V_6  [C0603]  64.42 31.91 270 top
C10627  *0.1U/6.3V_2  [C0201]  141.46 28.2 0 bottom
C10628  1U/6.3V_2  [C0201]  107.5 39.64 180 bottom
C10629  22u/25V_8  [C0805]  95.94 20.81 0 bottom
C10630  0.1u/25V_4  [C0402]  98.15 16.06 0 bottom
C10631  22u/10V_6  [C0603]  89.01 18.17 90 bottom
C10632  10u/25V_8  [C0805]  43.7 28.71 90 bottom
C10633  0.1u/25V_4  [C0402]  54.8 33.86 180 bottom
C10634  22u/10V_6  [C0603]  61.53 31.68 180 bottom
C10635  0.1U/6.3V_2  [C0201]  34.2 34.52 0 bottom
C10636  0.1U/6.3V_2  [C0201]  41.26 33.66 270 bottom
C10637  0.1u/50V_4  [C0402]  8.67 60.48 270 bottom
C10638  *100p/25V_2  [C0201]  133.23 61.27 90 top
C10639  1U/6.3V_2  [C0201]  39.48 39.12 270 top
C10640  10U/6.3V_6  [C0603]  39.81 41.99 180 top
C10641  *ECO@0.1U/6.3V_2  [C0201]  146.57 47.4 180 top
C10642  1U/6.3V_2  [C0201]  34.93 37.39 270 top
C10643  10p/50V_2  [C0201]  50.3 31.91 180 bottom
C10644  0.1U/6.3V_2  [C0201]  47.99 17.41 0 bottom
C10645  10p/50V_2  [C0201]  64.73 18.7 180 bottom
C10646  *47p/25V_2  [C0201]  92.31 16.9 180 bottom
C10647  *100p/25V_2  [C0201]  142.35 60.2 270 top
C10649  0.22u/6.3V_2  [C0201]  21.57 37.73 90 top
C10650  0.22u/6.3V_2  [C0201]  21.45 34.8 90 top
C10651  0.22u/6.3V_2  [C0201]  20.68 34.8 90 top
C10652  0.68u/6.3V_4  [C0402]  24.49 34.68 270 top
C10653  0.68u/6.3V_4  [C0402]  23.48 34.68 270 top
C10656  0.22u/6.3V_2  [C0201]  22.33 37.73 90 top
C10660  22u/10V_6  [C0603]  92.31 19.56 270 bottom
C10662  8200p/25V_4  [C0402]  101.33 20.96 0 bottom
C10663  0.1u/25V_4  [C0402]  57.39 44.58 90 bottom
C10664  *1U/6.3V_2  [C0201]  19.44 12.33 0 top
C10665  *1U/6.3V_2  [C0201]  15.71 13.44 180 top
C10666  *1u/50V_6  [C0603]  122.14 27.21 90 top
C10667  1U/6.3V_2  [C0201]  68.66 52.05 90 top
C10668  1U/6.3V_2  [C0201]  70.26 53.42 180 top
C10670  22u/10V_6  [C0603]  71.86 11.18 90 bottom
C10671  15p/50V_2  [C0201]  62.34 39 180 top
C10672  12p/50V_2  [C0201]  64.96 38.92 90 top
C10673  1U/6.3V_2  [C0201]  64.14 41.08 270 bottom
C10674  0.1U/6.3V_2  [C0201]  63.76 42.04 0 bottom
C10675  1N/50V_4  [C0402]  63.2 40.75 90 bottom
C10676  1N/50V_4  [C0402]  67.37 41 90 bottom
C10677  0.1U/6.3V_2  [C0201]  66.2 42.4 270 bottom
C10678  1U/6.3V_2  [C0201]  66.94 42.4 90 bottom
C10679  1N/50V_4  [C0402]  65.87 40.34 0 bottom
C10680  0.1U/6.3V_2  [C0201]  66.35 41.51 180 bottom
C10681  1U/6.3V_2  [C0201]  65.46 41.33 270 bottom
C10682  1N/50V_4  [C0402]  66.63 43.49 180 bottom
C10683  0.1U/6.3V_2  [C0201]  64.63 43.41 270 bottom
C10684  1U/6.3V_2  [C0201]  65.36 43.41 90 bottom
C10685  1N/50V_4  [C0402]  63.76 43.29 270 bottom
C10686  0.1U/6.3V_2  [C0201]  64.73 42.35 90 bottom
C10687  1U/6.3V_2  [C0201]  65.46 42.35 270 bottom
C10688  *GMR@0.1U/6.3V_2  [C0201]  126.47 66.94 270 top
C10689  *10p/50V_2  [C0201]  110.65 34.58 0 top
C10690  2200p/50V_4  [C0402]  62.04 15.58 90 bottom
C10691  10u/25V_8  [C0805]  58.58 15.88 90 bottom
C10692  0.1u/25V_2  [C0201]  62.9 15.58 270 bottom
C10693  22u/10V_6  [C0603]  73.39 11.18 90 bottom
C10694  0.1u/25V_4  [C0402]  64.24 19.59 180 bottom
C10695  10u/25V_8  [C0805]  45.68 28.71 90 bottom
C10696  0.1u/25V_2  [C0201]  48.09 28.99 270 bottom
C10697  22u/10V_6  [C0603]  61.53 28.56 180 bottom
C10698  22u/10V_6  [C0603]  61.53 29.98 180 bottom
C10699  0.33u/25V_2  [C0201]  20.43 21.47 180 top
C10700  0.33u/25V_2  [C0201]  20.43 22.23 180 top
C10701  0.33u/25V_2  [C0201]  21.57 22.61 180 top
C10702  0.33u/25V_2  [C0201]  21.57 23.37 180 top
C10703  0.68u/6.3V_4  [C0402]  18.88 20.43 0 top
C10704  0.68u/6.3V_4  [C0402]  18.88 21.44 0 top
C10705  0.68u/6.3V_4  [C0402]  19.79 23.12 0 top
C10706  0.68u/6.3V_4  [C0402]  19.79 24.14 0 top
C10707  0.68u/6.3V_4  [C0402]  19.64 36.76 270 top
C10708  0.68u/6.3V_4  [C0402]  18.68 36.76 270 top
C10709  0.1U/6.3V_2  [C0201]  42.4 19.06 0 bottom
C10710  4.7u/25V_6  [C0603]  129.09 36.02 0 top
C10711  0.1u/16V_4  [C0402]  73.64 43.44 90 bottom
C10712  22u/25V_8  [C0805]  114.28 24.64 315 bottom
C10713  22u/25V_8  [C0805]  115.81 26.17 315 bottom
C10714  22u/25V_8  [C0805]  114.03 11.44 90 bottom
C10715  22u/25V_8  [C0805]  69.83 22.61 90 bottom
C10716  0.1u/25V_2  [C0201]  25.51 41.74 270 bottom
C10717  1u/25V_4  [C0402]  22.08 41.92 90 bottom
C10718  *0.1u/25V_4  [C0402]  71.07 9.75 270 top
CHG_QONB_MTK  *TP  [TP2050]  51.16 17.41 180 bottom
CLIP9  *FBFG200601  [CLIP-39X39-89X20-3P]  85.35 23.36 0 top
CLIP10  *FBFG200601  [CLIP-39X39-89X20-3P]  105.16 66.66 0 top
CLIP11  *FBFG200601  [CLIP-39X39-89X20-3P]  74.81 55.23 90 top
CLIP12  *FBFG200601  [CLIP-39X39-89X20-3P]  74.81 34.91 90 top
CLIP17  *FBFG200601  [CLIP-39X39-89X20-3P]  117.86 34.91 90 top
CLIP19  *FBFG200601  [CLIP-39X39-89X20-3P]  117.86 55.23 90 top
CLIP20  *FBFG200601  [CLIP-39X39-89X20-3P]  101.86 23.36 0 top
CLIP21  *FBFG200601  [CLIP-39X39-89X20-3P]  88.65 66.66 0 top
CON12  50506-00601-V01  [FPC-50506-00601-V01-6P-L]  56.4 6.2 180 bottom
CON15  50458-00801-V02  [WTB-50458-00801-V02-8P-L]  98.7 6.02 180 bottom
CON16  AXK750147G  [AXK750147G-50P-LDV]  42.9 5.9 180 bottom
CON6201  2SJ3080-108111F  [AUDIO-2SJ3080-108111F-6P]  5.53 43.8 270 top
CON7101  AUSB0295-P007A  [UB31-AUSB0295-P007A-24P]  7.27 56.2 270 top
CON7102  51643-0300N-V01  [FPC-51643-0300N-V01-30P-L]  133.44 6.1 180 bottom
CON9104  50278-00401-V01  [50278-00401-001-4P-L]  27.12 5.17 180 bottom
CON9105  *51643-0300N-V01  [FPC-51643-0300N-V01-30P-L]  130.42 14.85 180 bottom
D1  AZ4024-01F.R7GR  [D-1X0_6-0_6H]  11.93 52.91 0 bottom
D7  R/G/B(12-23C/R6GHBHC-A01/2C  [LED-12-23C-R6GHY2C-A01-2C-4P]  4.05 34.92 90 top
D761  BAT54CT-7-F  [SOT23-1_38-5-3P]  132.8 35.57 270 top
D2705  CDBU00340-HF  [D-1_7X0_9]  45.32 21.34 0 bottom
D2706  CDBU00340-HF  [D-1_7X0_9]  61.63 17.48 270 top
D2707  CDBU00340-HF  [D-1_7X0_9]  115.58 47.46 90 top
D2708  CDBU00340-HF  [D-1_7X0_9]  103.51 26.28 0 top
D2711  MESD11LH5.0CT5G  [R0201]  144.25 8.77 270 top
D2712  MESD11LH5.0CT5G  [R0201]  143.37 8.77 270 top
D2713  MESD11LH5.0CT5G  [R0201]  142.5 9.91 90 top
D2714  MESD11LH5.0CT5G  [R0201]  145.14 8.77 270 top
D2715  MESD11LH5.0CT5G  [R0201]  137.73 9.71 90 top
D2716  MESD11LH5.0CT5G  [R0201]  139.86 9.71 90 top
D2717  MESD11LH5.0CT5G  [R0201]  139.05 9.71 90 top
D2718  MESD11LH5.0CT5G  [R0201]  141.59 9.91 90 top
D2719  MESD11LH5.0CT5G  [R0201]  134.37 9.91 90 top
D2720  MESD11LH5.0CT5G  [R0201]  136.81 9.91 90 top
D2721  MESD11LH5.0CT5G  [R0201]  135.19 9.91 90 top
D2722  MESD11LH5.0CT5G  [R0201]  136 9.91 90 top
D2723  MESD11LH5.0CT5G  [R0201]  132.14 9.91 90 top
D2724  MESD11LH5.0CT5G  [R0201]  130.72 9.91 90 top
D2725  MESD11LH5.0CT5G  [R0201]  133.56 9.91 90 top
D2726  MESD11LH5.0CT5G  [R0201]  131.43 9.91 90 top
D2727  MESD11LH5.0CT5G  [R0201]  129.29 9.91 90 top
D2728  MESD11LH5.0CT5G  [R0201]  127.67 9.91 90 top
D2729  MESD11LH5.0CT5G  [R0201]  130.01 9.91 90 top
D2730  MESD11LH5.0CT5G  [R0201]  128.48 9.91 90 top
D2731  MESD11LH5.0CT5G  [R0201]  125.43 9.91 90 top
D2732  MESD11LH5.0CT5G  [R0201]  126.86 9.91 90 top
D2733  MESD11LH5.0CT5G  [R0201]  124.72 9.91 90 top
D2734  MESD11LH5.0CT5G  [R0201]  123.3 9.91 90 top
D2736  CDBU00340-HF  [D-1_7X0_9]  57.39 24.52 0 top
D2737  CDBU00340-HF  [D-1_7X0_9]  5.7 22.79 0 top
D2738  CDBU00340-HF  [D-1_7X0_9]  44.38 37.52 180 top
D2739  CDBU00340-HF  [D-1_7X0_9]  41.41 37.52 0 top
D2740  AZ4024-01F.R7GR  [D-1X0_6-0_6H]  9.92 52.9 180 bottom
D2741  PESD5V0X2UM  [ESD3-0_985X0_585]  10.32 50.98 0 top
D2742  AZ4024-01F.R7GR  [D-1X0_6-0_6H]  9.13 50.3 180 bottom
D2743  AZ4024-01F.R7GR  [D-1X0_6-0_6H]  16.49 52.36 90 top
EMI7101  DLP11RN450UL2L  [CHOKE-DLP11RN450UL2L-4P]  16.04 50.09 180 top
ESD6204  *MESD11LH5.0CT5G  [R0201]  9.38 37.09 0 top
ESD6206  *MESD11LH5.0CT5G  [R0201]  15.73 28.2 180 top
ESD6309  *AZ4212-01F.R7G  [D-1X0_6-0_6H]  28.84 10.67 0 top
ESD6310  *AZ4212-01F.R7G  [D-1X0_6-0_6H]  26.02 10.65 180 top
ESD7102  PE3620M1Q  [D-1X0_6-D24V0L1B2LPS]  9.25 58.68 0 bottom
ESD7502  EGA10402V05AH  [R0402]  5.19 25.15 180 top
ESD7505  *AZ4212-01F.R7G  [D-1X0_6-0_6H]  23.86 10.65 0 top
ESD7506  *AZ4212-01F.R7G  [D-1X0_6-0_6H]  20.71 7.71 180 top
ESD7507  *MESD11LH5.0CT5G  [R0201]  6.92 32.39 180 top
ESD7508  MESD11LH5.0CT5G  [R0201]  14.99 33.48 180 top
ESD7509  *MESD11LH5.0CT5G  [R0201]  6.97 37.09 0 top
ESD7511  AZ4514-01F  [D-1_6X1]  89.37 15.09 90 bottom
EXT_PMIC_EN1  *TP  [TP2050]  102.65 35.01 90 top
F2  1812L150/24MR  [F4_55X3_24-5_23-1_8H]  60.23 44.1 90 bottom
FB1  30_100_BLM15PD300SN1D  [C0402]  20.99 18.95 180 top
FB2  30_100_BLM15PD300SN1D  [C0402]  21.83 15.4 270 bottom
FB3  30_100_BLM15PD300SN1D  [C0402]  19.87 19.97 180 bottom
FB4  30_100_BLM15PD300SN1D  [C0402]  20.68 18.95 180 bottom
FB5  30_100_BLM15PD300SN1D  [C0402]  22.84 15.4 270 bottom
HOLE7  *h-o118x157d118x157n  [H-O118X157D118X157N]  70.8 65.5 0 top
HOLE8  *H-C276D118P2  [H-C276D118P2]  149.34 22.85 0 top
HOLE9  *H-TC315IBC236D118P2  [H-TC315IBC236D118P2]  63.5 65.5 0 top
HOLE10  *H-C315D177P2  [H-C315D177P2]  11.45 5 0 top
HOLE11  *h-zde-1p2  [H-ZDE-1P2]  15.2 59.4 0 top
HOLE12  *H-C315D177P2  [H-C315D177P2]  82.6 5 0 top
HOLE13  *H-TC315IBC236D118P2  [H-TC315IBC236D118P2]  145 65.5 0 top
HOLE14  *H-C276D110P2  [H-C276D110P2]  62.22 56.16 0 top
HOLE15  *H-TC276IBC236D110P2  [H-TC276IBC236D110P2]  109.46 20.55 0 top
HOLE16  *spad-re295x472np  [SPAD-RE295X472NP]  149.55 54.01 180 top
HOLE17  *2D-BARCODE-8X8-S  [2D-BARCODE-8X8-S]  140.62 53.78 270 top
HOLE18  *2D-BARCODE-8X8-S  [2D-BARCODE-8X8-S]  8.7 29.24 270 bottom
HOLE19  *SPAD-RE394X118NP  [SPAD-RE394X118NP]  55.8 1.5 0 top
HOLE20  *SPAD-RE197X787NP  [SPAD-RE197X787NP]  132.79 6.5 90 top
HUB_SDA  *TP  [TP2050]  67.7 31.83 90 top
HUB_TEST  *TP  [TP2050]  72.37 28.58 0 top
I2C1_SCL_MTK  *TP  [TP2050]  79.61 33.28 0 top
I2C1_SDA_MTK  *TP  [TP2050]  78.37 32.14 0 top
I2C6_SCL_MTK  *TP  [TP2050]  94.04 38.28 0 top
I2C6_SDA_MTK  *TP  [TP2050]  94.04 37.01 0 top
J15  51693-04001-V01  [51693-04001-V01-40P-L]  43.8 41.8 0 bottom
J17  50696-0200M-V02  [50696-0200M-V02-20P-L]  151.32 32.7 270 bottom
J20  *2CM@50208-00601-V02  [50208-00601-V02-6P-L]  118.5 65.35 0 bottom
J24  *50208-00601-V02  [50208-00601-V02-6P-L]  128.3 65.25 0 bottom
L12  *2CM@DLP11SA900HL2L  [CHOKE-DLP11SN900HL2L-4P-1]  115.76 61.55 180 bottom
L16  1.5UH_2.5x2.0x1.2  [L2_5X2-1_2]  69.2 36.58 180 top
L48  2.2uH_10x10x2  [L10_1X10-2H-SMT]  135.36 29.52 270 bottom
L6904  BLM15HG102SN1D  [R0402]  111.74 33.31 270 top
NC63  *NC_PAD  [S0201]  96.88 12.73 90 bottom
NC245  *PAD  [S0201]  22.08 46.36 90 top
NC246  *PAD  [S0201]  21.06 46.36 90 top
NC247  *PAD  [S0201]  52.84 23.78 90 top
NC248  *PAD  [S0201]  51.77 23.78 90 top
NC249  *PAD  [S0201]  53.58 11.18 270 top
NC250  *PAD  [S0201]  54.59 11.18 270 top
NC251  *PAD  [S0201]  119.52 52.71 180 top
NC252  *PAD  [S0201]  119.52 51.44 180 top
NC255  *NC_PAD  [S0201]  100.59 48.78 0 top
NC256  *NC_PAD  [S0201]  100.59 50.08 0 top
NC266  *NC_PAD  [S0201]  44.53 32.92 90 bottom
NC267  *NC_PAD  [S0201]  45.6 32.92 90 bottom
NC268  *NC_PAD  [S0201]  45.19 39.76 0 top
NC269  *NC_PAD  [S0201]  45.19 40.77 0 top
NC270  *PAD  [S0201]  105.19 48.32 0 top
NC271  *PAD  [S0201]  105.19 49.39 0 top
NC272  *PAD  [S0201]  131.29 57.25 180 top
NC273  *PAD  [S0201]  131.29 58.52 180 top
NC274  *PAD  [S0201]  118.02 61.04 90 bottom
NC275  *PAD  [S0201]  119.34 61.04 90 bottom
NC279  *NC_PAD  [S0201]  130.54 23.25 180 bottom
NC280  *NC_PAD  [S0201]  126.09 27.44 270 top
NC281  *NC_PAD  [S0201]  128.13 28.45 0 top
NC282  *NC_PAD  [S0201]  129.47 32.8 0 top
NC283  *NC_PAD  [S0201]  129.57 30.31 0 top
NC284  *NC_PAD  [S0201]  129.57 29.6 180 top
NC287  *NC_PAD  [S0201]  88.63 11.66 0 bottom
NC288  *NC_PAD  [S0201]  88.63 12.68 0 bottom
NC291  *NC_PAD  [S0201]  104.63 17.66 0 bottom
NC292  *NC_PAD  [S0201]  104.63 16.52 0 bottom
NC293  *NC_PAD  [S0201]  56.55 35.01 180 bottom
NC294  *NC_PAD  [S0201]  56.55 33.99 180 bottom
NC295  *NC_PAD  [S0201]  86.22 17.79 180 bottom
NC296  *NC_PAD  [S0201]  86.22 18.68 180 bottom
NC302  *NC_PAD  [S0201]  59.06 39.6 180 bottom
NC303  *NC_PAD  [S0201]  59.06 37.83 180 bottom
NOREF  -  [unnamed]  26.3 43.83 180 top
NOREF#2  -  [unnamed]  82.53 32.41 270 top
NOREF#3  -  [unnamed]  63.64 44.47 90 top
NOREF#4  -  [unnamed]  63.01 43.54 180 top
NOREF#5  -  [unnamed]  24.89 4.62 90 top
NOREF#6  -  [unnamed]  91.39 40.94 180 top
NOREF#7  -  [unnamed]  12.54 29.09 0 top
NOREF#8  -  [unnamed]  146.92 13.21 0 top
NOREF#9  -  [unnamed]  125.15 47.62 90 top
NOREF#10  -  [unnamed]  32.36 11.38 90 top
NOREF#11  -  [unnamed]  64 40.37 90 top
NOREF#12  -  [#2]  227.39 -67.05 0 top
NOREF#13  -  [unnamed]  17.69 6.08 0 top
NOREF#14  -  [unnamed]  149.02 43.55 0 top
NOREF#15  -  [unnamed]  98.09 53.81 270 top
NOREF#16  -  [unnamed]  11.57 24.4 90 top
NOREF#17  -  [unnamed]  104.28 41.9 270 top
NOREF#18  -  [unnamed]  111.2 65.41 90 top
NOREF#19  -  [unnamed]  126.6 64.4 0 top
NOREF#20  -  [#2]  51.76 -54.36 0 top
NOREF#21  -  [unnamed]  56.43 19.96 90 top
NOREF#22  -  [#2]  137.04 39.12 0 top
NOREF#23  -  [unnamed]  147.36 43.43 0 top
NOREF#24  -  [unnamed]  89.88 44.31 90 top
NOREF#25  -  [unnamed]  11.4 26.16 90 top
NOREF#26  -  [unnamed]  127.52 52.72 270 top
NOREF#27  -  [unnamed]  109.88 35.66 0 top
NOREF#28  -  [unnamed]  26.1 45.01 90 top
NOREF#29  -  [unnamed]  52.93 14.85 270 top
NOREF#30  -  [unnamed]  128.14 51.36 180 top
NOREF#31  -  [unnamed]  10.8 30.57 0 top
NOREF#32  -  [unnamed]  148.95 13.09 180 bottom
NOREF#33  -  [unnamed]  30.08 46.74 180 bottom
NOREF#34  -  [unnamed]  112.07 66.33 180 bottom
NOREF#35  -  [#2]  96.88 60.71 180 bottom
NTC1501  100K_NTC_1%_4  [R0402]  80.01 25.52 90 top
NTC1502  100K_NTC_1%_4  [R0402]  119.21 49.1 270 top
PC18  *680p/50V_6  [C0603]  68.41 10.57 0 bottom
PC131  4.7U/6.3V_4  [C0402_2]  66.86 19.23 270 bottom
PC132  0.1u/16V_4  [C0402]  74.66 11.31 90 bottom
PC133  1u/10V_4  [C0402]  65.72 19.23 270 bottom
PC134  *680p/50V_6  [C0603]  58.53 26.75 180 bottom
PC135  0.1u/16V_4  [C0402]  61.1 32.87 180 bottom
PC136  4.7U/6.3V_4  [C0402_2]  51.39 32.47 270 bottom
PC137  1u/10V_4  [C0402]  48.93 31.93 0 bottom
PC138  1u/10V_4  [C0402]  69.86 5.24 0 top
PC139  1u/10V_4  [C0402]  65.97 6.53 0 top
PC140  4.7U/6.3V_4  [C0402_2]  51.27 30.64 90 top
PL2001  0.47UH_2.0X1.6X1  [L2X1_6-1H-2P]  100.06 36.74 180 top
PL2002  0.47UH_2.0X1.6X1  [L2X1_6-1H-2P]  100.06 39.26 180 top
PL2003  0.47UH_2.0X1.6X1  [L2X1_6-1H-2P]  100.8 44.29 180 top
PL2006  1UH_2.5x2.0x1  [L2_5X2-1-HTEN25201T]  101.91 32.98 270 top
PL2007  1UH_2.5x2.0x1  [L2_5X2-1-HTEN25201T]  110.14 46.7 90 top
PL2008  0.47UH_2.0X1.6X1  [L2X1_6-1H-2P]  100.06 41.77 180 top
PL2009  1UH_2.5x2.0x1  [L2_5X2-1-HTEN25201T]  107.02 46.19 90 top
PL2702  1uH_5x5x1.8  [L5_1X5_2-1_6H]  71.2 15.83 0 bottom
PL2703  2.2uH_3x3x1.2  [L3_1X3_1]  95.44 18.01 180 bottom
PL2704  1uH_5x5x1.8  [L5_1X5_2-1_6H]  56.88 30.33 0 bottom
PP1800_ALW_PG  *TP  [TP2050]  99.93 21.09 180 bottom
PP3300_ALW_PG  *TP  [TP2050]  48.83 31.12 0 bottom
PP5000_ALW_PG1  *TP  [TP2050]  63.05 19.54 180 bottom
PQ1  AONY36356  [POWER-5_2X5_55-1_27-7P-1H]  128.51 37.73 90 bottom
PQ2  AONY36356  [POWER-5_2X5_55-1_27-7P-1H]  127.24 26.17 180 bottom
PR23  *4.7_5%_6  [R0603]  70.44 11.18 90 bottom
PR158  10_1%_6  [R0603]  68.77 19.44 0 bottom
PR263  10_1%_6  [R0603]  52.51 34.04 0 bottom
PR264  *4.7_5%_6  [R0603]  55.86 26.75 180 bottom
PU1  RT9078-18GJ5  [SOT23-5-2_794-9395-5P]  69.38 7.45 0 top
Q2  PJE138K  [SOT23-1_38-5-3P]  26.4 28.2 0 bottom
Q3  PMDXB600UNE  [DFN6-1_1X1-35-SMT]  24.62 18.04 270 bottom
Q4  PMDXB600UNE  [DFN6-1_1X1-35-SMT]  26.65 17.91 180 bottom
Q8  PMZB670UPE  [DFN1006-3-1X0_6-3P]  37.88 7.17 0 top
Q55  2N7002K  [SOT23-2-95-3P]  97.47 9.48 270 top
Q80  *PMDXB600UNE  [DFN6-1_1X1-35-SMT]  39.99 13.01 90 bottom
Q81  *PMDXB600UNE  [DFN6-1_1X1-35-SMT]  39.99 5.34 180 top
Q705  PJE138K  [SOT23-1_38-5-3P]  41.33 39.55 270 top
Q706  PJE138K  [SOT23-1_38-5-3P]  43.54 39.55 270 top
Q717  PMZB670UPE  [DFN1006-3-1X0_6-3P]  51.16 20.33 180 top
Q718  PJE138K  [SOT23-1_38-5-3P]  78.72 38.57 90 top
Q723  PJE138K  [SOT23-1_38-5-3P]  131.86 63.66 90 top
Q724  PJE138K  [SOT23-1_38-5-3P]  135.08 64.04 90 top
Q725  *PJE138K  [SOT23-1_38-5-3P]  149.97 34.68 180 top
Q726  *PJE138K  [SOT23-1_38-5-3P]  149.97 32.39 180 top
Q727  PJE138K  [SOT23-1_38-5-3P]  42.53 6.48 90 top
Q730  PMZ370UNE  [ESD3-0_985X0_585]  53.2 7.5 0 top
Q731  PMZ370UNE  [ESD3-0_985X0_585]  53.2 5.98 0 top
Q732  PMZ370UNE  [ESD3-0_985X0_585]  53.4 3.71 0 top
Q734  PMZ370UNE  [ESD3-0_985X0_585]  51.67 3.71 180 top
Q739  PMDXB600UNE  [DFN6-1_1X1-35-SMT]  123.3 43.44 90 top
Q748  *PJE138K  [SOT23-1_38-5-3P]  48.75 9.66 0 top
Q750  PMZB670UPE  [DFN1006-3-1X0_6-3P]  121.06 57.56 270 top
Q757  PJE138K  [SOT23-1_38-5-3P]  143.7 23.88 90 top
Q759  PJE138K  [SOT23-1_38-5-3P]  143.75 27.18 90 top
Q762  PMZ370UNE  [ESD3-0_985X0_585]  61.32 10.17 0 top
Q763  PMZ370UNE  [ESD3-0_985X0_585]  56.88 9.07 270 top
Q766  PMZ370UNE  [ESD3-0_985X0_585]  62.06 19.82 90 bottom
Q767  PMZ370UNE  [ESD3-0_985X0_585]  51.42 5.98 180 top
Q768  PMZ370UNE  [ESD3-0_985X0_585]  51.42 7.5 180 top
Q776  TS@PMDXB600UNE  [DFN6-1_1X1-35-SMT]  42.4 47.4 90 top
Q777  TS@PMDXB600UNE  [DFN6-1_1X1-35-SMT]  45.98 47.4 270 top
Q778  TS@PMDXB600UNE  [DFN6-1_1X1-35-SMT]  50.27 47.63 0 top
Q779  TS@PMDXB600UNE  [DFN6-1_1X1-35-SMT]  54.21 47.63 0 top
Q780  PJE138K  [SOT23-1_38-5-3P]  15.43 28.05 0 bottom
Q781  PJE138K  [SOT23-1_38-5-3P]  15.4 30.33 0 bottom
Q782  PJE138K  [SOT23-1_38-5-3P]  15.4 32.62 0 bottom
Q783  PJE138K  [SOT23-1_38-5-3P]  20.18 37.6 180 bottom
Q784  PJE138K  [SOT23-1_38-5-3P]  20.18 35.31 180 bottom
Q785  *2N7002K  [SOT23-2-95-3P]  91.93 8.77 0 top
Q786  *PJE138K  [SOT23-1_38-5-3P]  144.64 37.85 0 top
Q787  PJE138K  [SOT23-1_38-5-3P]  141.46 23.88 90 top
Q788  PJE138K  [SOT23-1_38-5-3P]  141.46 27.18 90 top
Q789  AONR21357  [POWER-3X3-65-5P-ADNR21357]  32.57 39.6 270 top
Q790  PJE138K  [SOT23-1_38-5-3P]  26.45 47.5 90 top
Q791  PJE138K  [SOT23-1_38-5-3P]  56.62 38.36 270 top
Q792  PJE138K  [SOT23-1_38-5-3P]  53.27 37.17 180 top
Q793  PJE138K  [SOT23-1_38-5-3P]  129.78 56.01 180 top
Q794  PJE138K  [SOT23-1_38-5-3P]  126.47 55.73 180 top
Q795  *PJE138K  [SOT23-1_38-5-3P]  31.71 47.5 90 top
Q797  PJE138K  [SOT23-1_38-5-3P]  101.84 14.23 0 top
Q798  PJE138K  [SOT23-1_38-5-3P]  63.48 22.38 90 bottom
Q799  PMDXB600UNE  [DFN6-1_1X1-35-SMT]  63.79 45.98 90 bottom
Q800  PMDXB600UNE  [DFN6-1_1X1-35-SMT]  67.01 46.01 90 bottom
Q801  *AONR21357  [POWER-3X3-65-5P-ADNR21357]  28.05 40.57 0 top
Q802  PJE138K  [SOT23-1_38-5-3P]  43.16 17.15 0 bottom
Q803  PJE138K  [SOT23-1_38-5-3P]  44.18 19.44 180 bottom
Q804  AO3415  [SOT23-2_38-95-3P]  48.83 30.44 270 top
Q805  AO3415  [SOT23-2_38-95-3P]  52.48 28.4 270 top
Q806  PMZ370UNE  [ESD3-0_985X0_585]  49.74 27.18 180 top
Q807  PMZ370UNE  [ESD3-0_985X0_585]  54.21 15.6 0 bottom
Q808  PMZ370UNE  [ESD3-0_985X0_585]  54.21 12.86 0 bottom
R1  100K_1%_2  [R0201]  19.92 25.91 180 top
R2  100K_1%_2  [R0201]  19.92 25.15 180 top
R3  10K_1%_2  [R0201]  28.43 15.12 270 top
R4  820_1%_4  [R0402]  23.35 20.07 270 bottom
R10  *Short_0201  [S0201]  24.11 28.86 180 top
R12  *Short_0201  [S0201]  25 15.37 270 bottom
R13  *Short_0201  [S0201]  25.76 15.37 270 bottom
R15  4.7K_5%_2  [R0201]  24.24 14.99 90 top
R17  1M_1%_4  [R0402]  21.9 16.31 90 top
R20  22K_1%_4  [R0402]  24.62 28.58 90 bottom
R102  *Short_0402  [S0402]  36.86 34.4 0 bottom
R174  6.04K_1%_2  [R0201]  121.14 31.6 270 top
R184  *Short_0201  [S0201]  69.15 39.63 180 top
R185  *Short_0201  [S0201]  69.15 40.34 180 top
R187  *Short_0201  [S0201]  69.15 45.73 180 top
R188  *Short_0201  [S0201]  69.15 46.44 180 top
R189  *Short_0201  [S0201]  69.15 42.68 180 top
R190  *Short_0201  [S0201]  69.15 43.39 180 top
R191  *Short_0201  [S0201]  69.15 41.15 180 top
R192  *Short_0201  [S0201]  69.15 44.2 180 top
R193  *Short_0201  [S0201]  69.15 44.91 180 top
R194  *Short_0201  [S0201]  69.15 41.87 180 top
R215  *Short_0402  [S0402]  70.98 34.4 180 top
R217  100K_1%_2  [R0201]  72.04 35.44 270 top
R218  *Short_0402  [S0402]  72.63 40.65 270 top
R219  147K_1%_2  [R0201]  72.75 35.44 270 top
R252  *0_5%_2  [R0201]  46.21 43.69 90 top
R277  *Short_0201  [S0201]  141.46 27.44 0 bottom
R293  1M_1%_4  [R0402]  110.73 8.97 270 bottom
R313  0_5%_4  [R0402]  45.19 6.48 90 top
R314  0_5%_4  [R0402]  44.18 6.48 90 top
R323  0_5%_2  [R0201]  40.14 7.5 270 top
R330  *Short_0402  [S0402]  44.69 12.71 270 bottom
R331  *Short_0402  [S0402]  45.83 11.82 270 bottom
R332  *Short_0402  [S0402]  46.97 4.71 0 top
R334  10K_1%_4  [R0402]  47.48 13.85 270 top
R338  *Short_0402  [S0402]  60.51 14.76 270 top
R350  47K_1%_2  [R0201]  45.7 22.99 0 top
R391  *Short_0805  [S0805]  59.95 38.59 270 bottom
R405  93.1K_1%_4  [R0402]  120.43 34.93 270 top
R420  100K_1%_2  [R0201]  94.09 8.26 90 top
R442  *0_5%_2  [R0201]  35.67 28.84 270 top
R443  *0_5%_2  [R0201]  36.43 28.84 270 top
R476  *Short_0402  [S0402]  40.27 3.94 180 top
R503  392K_1%_4  [R0402]  123.55 39.88 90 top
R504  120K_1%_4  [R0402]  123.57 36.42 270 top
R512  *Short_0402  [S0402]  38.46 11.82 270 bottom
R521  *0_5%_2  [R0201]  122.51 37.28 90 top
R537  100K_1%_2  [R0201]  121.27 36.04 270 top
R538  *0_5%_2  [R0201]  120.38 36.4 0 top
R612  0.01_1%_6  [R0603]  102.17 14.92 0 bottom
R619  100K_1%_2  [R0201]  23.37 44.1 180 top
R654  0.02_1%_6  [R0603]  36.05 46.44 270 top
R707  4.7_1%_6  [R0603]  131.3 26.93 180 top
R709  *Short_0201  [S0201]  121.99 36.04 270 top
R720  0_5%_6  [R0603]  129.68 33.86 0 top
R721  0_5%_6  [R0603]  123.55 27.21 270 top
R940  4.7K_5%_2  [R0201]  23.81 28.12 0 top
R941  4.7K_5%_2  [R0201]  17.25 34.3 270 top
R942  4.7K_5%_2  [R0201]  16.49 34.3 270 top
R1001  12K_5%_2  [R0201]  96.27 39.88 0 top
R1004  *12K_5%_2  [R0201]  95.26 39.88 0 top
R1007  *12K_5%_2  [R0201]  96.27 39.17 0 top
R1009  *12K_5%_2  [R0201]  95.87 41.92 0 top
R1010  12K_5%_2  [R0201]  95.54 38.46 0 top
R1011  12K_5%_2  [R0201]  94.34 40.7 90 top
R1012  12K_5%_2  [R0201]  94.75 41.92 0 top
R1101  *4.7K_5%_2  [R0201]  76.74 37.4 0 top
R1102  *4.7K_5%_2  [R0201]  76.74 38.16 0 top
R1103  *2.2K_5%_2  [R0201]  76.33 31.82 180 top
R1104  *2.2K_5%_2  [R0201]  78.65 33.51 180 top
R1105  *4.7K_5%_2  [R0201]  78.32 35.19 0 top
R1106  *4.7K_5%_2  [R0201]  78.32 34.48 0 top
R1107  *4.7K_5%_2  [R0201]  88.68 27.16 90 top
